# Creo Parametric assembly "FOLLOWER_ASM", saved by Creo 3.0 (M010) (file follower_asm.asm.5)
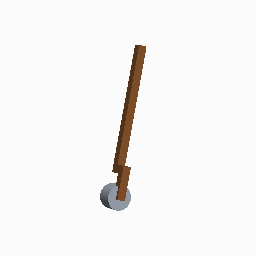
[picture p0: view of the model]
Units: millimeter Kilogram Sec (mmKs); MM, KILOGRAM, SECS

Created from: MMKS_ASM_DESIGN.ASM

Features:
  1. datum plane "ASM_RIGHT"
  2. datum plane "ASM_TOP"
  3. datum plane "ASM_FRONT"
  4. coordinate system
  5. component "FOLLOWER_BAR"
  6. component "FOLLOWER_ROLLER"

Family table entries: GENERIC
